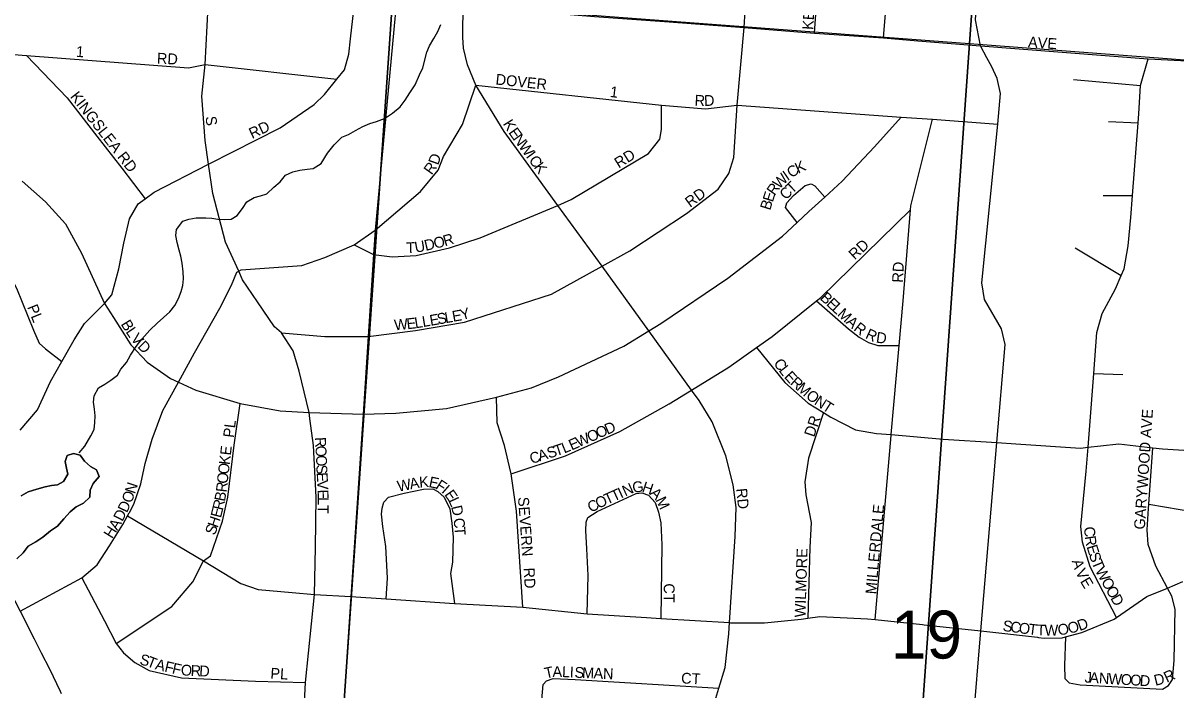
# Model space of a CAD drawing. Extents: x 0 to 34, y 0 to 22.
# Drawn here: x 4.06 to 5.068, y 19.645 to 20.227 of the extents above; entities that cross this region are included whole.
import ezdxf

# ---------------------------------------------------------------- set-up
doc = ezdxf.new("R2010")
doc.units = 0
for name, color, linetype in [('GM_X_City_Street', 7, 'Continuous'), ('GM_X_City_Street_Text', 7, 'Continuous'), ('GM_X_Minor_Lake', 7, 'Continuous'), ('GM_X_Section', 7, 'Continuous'), ('GM_X_Section_Text', 7, 'Continuous'), ('GM_X_Township', 7, 'Continuous'), ('GM_X_US_Route', 7, 'Continuous')]:
    doc.layers.add(name, color=color, linetype=linetype)

msp = doc.modelspace()

# ---------------------------------------------------------------- linework, layer by layer
at = {"layer": 'GM_X_City_Street'}
for points in [[(4.6908, 20.2235), (4.6971, 20.3256), (4.7014, 20.3449), (4.7083, 20.3621), (4.7157, 20.3809), (4.7159, 20.3828), (4.7163, 20.3877), (4.7225, 20.4452), (4.7281, 20.4967), (4.734, 20.551), (4.7395, 20.6016), (4.7397, 20.603), (4.7454, 20.6575), (4.7514, 20.7146), (4.7558, 20.7568), (4.7554, 20.7682), (4.7496, 20.7774), (4.7304, 20.8076), (4.7253, 20.8173), (4.7253, 20.8196), (4.7291, 20.8815)], [(4.8977, 20.2074), (4.8932, 20.2301), (4.9003, 20.33), (4.9074, 20.4285), (4.9121, 20.5032), (4.9139, 20.5324), (4.9208, 20.6443), (4.9237, 20.6899), (4.9244, 20.6989), (4.9384, 20.8789)], [(4.8128, 20.2144), (4.818, 20.2779), (4.8184, 20.3024), (4.823, 20.3174), (4.8309, 20.3384), (4.8395, 20.3614), (4.8435, 20.3818), (4.8426, 20.3913), (4.8402, 20.3997)], [(4.7525, 20.2185), (4.7588, 20.3095), (4.7569, 20.325), (4.7614, 20.337), (4.7725, 20.3626)], [(3.7534, 20.2931), (3.8331, 20.288), (3.8627, 20.2861), (3.9076, 20.2829), (3.9707, 20.2779), (4.0334, 20.2728), (4.097, 20.2682), (4.1591, 20.2638), (4.2232, 20.259), (4.2902, 20.2539), (4.3507, 20.2493), (4.387, 20.2468), (4.4457, 20.2423), (4.5601, 20.2332), (4.6254, 20.2285), (4.6908, 20.2235), (4.7525, 20.2185), (4.8128, 20.2144), (4.8427, 20.2119)], [(4.3112, 19.8818), (4.3105, 19.8869), (4.3017, 19.923), (4.2966, 19.9408), (4.2863, 19.9566), (4.2801, 19.962), (4.2654, 19.9837), (4.2522, 20.0031), (4.2489, 20.0105), (4.2375, 20.0358), (4.2263, 20.0783), (4.2226, 20.104), (4.2196, 20.1247), (4.2167, 20.1634), (4.2196, 20.191), (4.2232, 20.259)], [(4.0578, 19.8716), (4.073, 19.8894), (4.0844, 19.9141), (4.0943, 19.9316), (4.105, 19.9504), (4.1141, 19.9648), (4.1316, 19.9822), (4.1381, 19.9898), (4.1442, 20.0126), (4.1485, 20.0349), (4.1535, 20.0562), (4.1611, 20.0695), (4.1671, 20.0738), (4.1751, 20.0796), (4.2226, 20.104), (4.223, 20.1042), (4.2852, 20.1359), (4.3148, 20.1562), (4.3239, 20.1649), (4.3346, 20.1782), (4.3414, 20.1865), (4.3453, 20.2002), (4.3468, 20.2135), (4.3507, 20.2493)], [(4.6625, 19.6256), (4.6687, 19.646), (4.6744, 19.6642), (4.6775, 19.6935), (4.6781, 19.7034), (4.6831, 19.7785), (4.6839, 19.8039), (4.6813, 19.8237), (4.675, 19.8491), (4.6629, 19.8788), (4.6516, 19.8974), (4.645, 19.9066), (4.6076, 19.9583), (4.5666, 20.0148), (4.5281, 20.068), (4.4811, 20.1326), (4.4564, 20.1731), (4.4489, 20.1908), (4.4456, 20.2055), (4.4449, 20.215), (4.4449, 20.2273), (4.4457, 20.2423)], [(4.2863, 19.9566), (4.3243, 19.9534), (4.3621, 19.9533), (4.4034, 19.9586), (4.4464, 19.966), (4.5223, 19.9904), (4.5666, 20.0148), (4.591, 20.0282), (4.6404, 20.061), (4.6681, 20.0822), (4.6776, 20.0958), (4.6819, 20.1099), (4.6848, 20.1556), (4.6908, 20.2235)], [(3.9615, 20.2216), (3.9804, 20.2082), (3.9902, 20.2036), (4.0111, 20.2032), (4.0633, 20.1991), (4.205, 20.1881), (4.2196, 20.191), (4.3346, 20.1782)], [(4.8427, 20.2119), (4.8977, 20.2074), (5.0441, 20.196), (5.0784, 20.1943), (5.1422, 20.1904), (5.1677, 20.188), (5.203, 20.1861), (5.2651, 20.1817), (5.3905, 20.173), (5.4941, 20.1636), (5.6037, 20.1551), (5.6314, 20.1529)], [(4.905, 19.5357), (4.9012, 19.5594), (4.8985, 19.5762), (4.8896, 19.5952), (4.891, 19.6145), (4.8911, 19.6152), (4.8979, 19.6961), (4.9119, 19.8608), (4.9191, 19.9465), (4.9159, 19.9602), (4.9011, 19.9858), (4.8986, 20.0003), (4.9127, 20.1391), (4.9152, 20.1659), (4.9122, 20.179), (4.9074, 20.189), (4.903, 20.1971), (4.8977, 20.2074)], [(4.0633, 20.1991), (4.0989, 20.1619), (4.1249, 20.1284), (4.1468, 20.1006), (4.1671, 20.0738)], [(5.0164, 19.7078), (4.9936, 19.7521), (4.9868, 19.7737), (4.9853, 19.7874), (4.99, 19.8356), (4.9916, 19.8566), (4.9967, 19.9212), (4.9994, 19.9568), (5.004, 19.9735), (5.0155, 19.9951), (5.0205, 20.0067), (5.0231, 20.0125), (5.0266, 20.0326), (5.0289, 20.0573), (5.0304, 20.0767), (5.0354, 20.1401), (5.036, 20.1481), (5.0376, 20.1727), (5.0441, 20.196)], [(4.1532, 19.7992), (4.1534, 19.7997), (4.1572, 19.8068), (4.1633, 19.8246), (4.1672, 19.8424), (4.1733, 19.8637), (4.1825, 19.8887), (4.1962, 19.9136), (4.2103, 19.9391), (4.2324, 19.9781), (4.2427, 19.9982), (4.2473, 20.0096), (4.2489, 20.0105), (4.2511, 20.0118), (4.3041, 20.0155), (4.3241, 20.0224), (4.35, 20.0335), (4.3683, 20.0465), (4.4079, 20.0802), (4.4234, 20.0987), (4.428, 20.1107), (4.4447, 20.1387), (4.4564, 20.1731)], [(4.4564, 20.1731), (4.6187, 20.1555), (4.657, 20.1525), (4.6848, 20.1556), (4.8283, 20.145), (4.8555, 20.1434), (4.9127, 20.1391)], [(4.9788, 20.1779), (5.0376, 20.1727)], [(4.35, 20.0335), (4.3668, 20.0251), (4.3831, 20.0231), (4.4042, 20.0243), (4.4333, 20.0308), (4.46, 20.0396), (4.5281, 20.068), (4.5396, 20.0731), (4.6072, 20.1135), (4.6171, 20.126), (4.6186, 20.1344), (4.6187, 20.1555)], [(4.0596, 20.0891), (4.08, 20.0712), (4.0974, 20.0518), (4.1113, 20.0263), (4.1316, 19.9822), (4.1395, 19.9701), (4.1546, 19.9461), (4.169, 19.9309), (4.1894, 19.9168), (4.1962, 19.9136), (4.2113, 19.9064), (4.2503, 19.8949), (4.2852, 19.8885), (4.3105, 19.8869), (4.3576, 19.8857), (4.3862, 19.8863), (4.4305, 19.8904), (4.4742, 19.9005), (4.505, 19.9086), (4.5285, 19.9183), (4.5858, 19.9451), (4.6076, 19.9583), (4.6181, 19.9647), (4.6766, 20.0044), (4.7244, 20.041), (4.7374, 20.0531), (4.7476, 20.0626), (4.7615, 20.0753), (4.7765, 20.0891), (4.805, 20.1193), (4.8283, 20.145)], [(4.8056, 19.706), (4.8194, 19.8669), (4.8195, 19.8677), (4.8265, 19.9456), (4.83, 19.9845), (4.8364, 20.0641), (4.8367, 20.0676), (4.8555, 20.1434)], [(5.0094, 20.1413), (5.0354, 20.1401)], [(3.8939, 20.1247), (3.9115, 20.106), (3.9531, 20.0758), (4.0393, 20.0178), (4.0476, 20.0087), (4.0547, 19.9958), (4.0694, 19.9589), (4.0743, 19.9475), (4.08, 19.9426), (4.0943, 19.9316)], [(4.7374, 20.0531), (4.7272, 20.0661), (4.7283, 20.0702), (4.734, 20.0767), (4.7443, 20.0854), (4.7496, 20.0869), (4.7526, 20.085), (4.7615, 20.0753)], [(5.0047, 20.0768), (5.0304, 20.0767)], [(4.4871, 19.8333), (4.5348, 19.8492), (4.5823, 19.8703), (4.6252, 19.8945), (4.645, 19.9066), (4.6776, 19.9266), (4.7017, 19.9438), (4.7153, 19.9534), (4.7543, 19.9846), (4.7579, 19.9875), (4.8364, 20.0641)], [(4.9803, 20.0309), (5.0205, 20.0067)], [(4.7543, 19.9846), (4.7821, 19.9601), (4.7915, 19.9528), (4.7995, 19.9482), (4.8078, 19.9456), (4.8265, 19.9456)], [(4.7017, 19.9438), (4.7265, 19.9132), (4.747, 19.8952), (4.7603, 19.887), (4.7667, 19.883), (4.7883, 19.8719), (4.8065, 19.8688), (4.8195, 19.8677), (4.8649, 19.8637), (4.9119, 19.8608), (4.9286, 19.8597), (4.9851, 19.8558), (4.9916, 19.8566), (5.0026, 19.858), (5.0185, 19.8595), (5.0483, 19.8561), (5.0568, 19.8552), (5.1362, 19.8504)], [(4.9967, 19.9212), (5.0221, 19.9202)], [(4.1418, 19.6852), (4.1903, 19.7175), (4.2089, 19.739), (4.218, 19.7574), (4.2241, 19.7618), (4.2348, 19.7921), (4.2395, 19.813), (4.2449, 19.8585), (4.2503, 19.8949)], [(4.4974, 19.7169), (4.4918, 19.8007), (4.4871, 19.8333), (4.487, 19.8345), (4.4814, 19.8581), (4.475, 19.8779), (4.4742, 19.9005)], [(4.3809, 19.4652), (4.3713, 19.4859), (4.3604, 19.4991), (4.3474, 19.5119), (4.3336, 19.5245), (4.3232, 19.5402), (4.3146, 19.5588), (4.3093, 19.5755), (4.3058, 19.59), (4.3051, 19.6047), (4.3074, 19.651), (4.3153, 19.728), (4.3162, 19.7691), (4.3165, 19.8131), (4.3143, 19.8581), (4.3112, 19.8818)], [(4.7603, 19.887), (4.7472, 19.847), (4.7441, 19.8265), (4.7449, 19.8151), (4.7494, 19.7908), (4.7482, 19.7691), (4.7467, 19.7073)], [(5.062, 19.6485), (5.0654, 19.6538), (5.067, 19.6702), (5.0678, 19.715), (5.0648, 19.7264), (5.061, 19.7336), (5.0509, 19.7526), (5.0441, 19.7716), (5.0434, 19.7846), (5.0446, 19.8032), (5.0448, 19.8068), (5.0483, 19.8561)], [(4.378, 19.7241), (4.379, 19.7423), (4.3776, 19.77), (4.375, 19.7875), (4.3739, 19.7981), (4.3743, 19.8034), (4.3759, 19.8087), (4.38, 19.8129), (4.3937, 19.8166), (4.4104, 19.82), (4.4187, 19.8203), (4.4229, 19.8181), (4.4285, 19.8131), (4.4334, 19.8028), (4.4353, 19.7903), (4.4364, 19.7782), (4.4359, 19.7561), (4.434, 19.7463), (4.4375, 19.72)], [(4.5536, 19.711), (4.5545, 19.7447), (4.5534, 19.7679), (4.5524, 19.7838), (4.5528, 19.7911), (4.5543, 19.7952), (4.5623, 19.8005), (4.5964, 19.8163), (4.6013, 19.8167), (4.6074, 19.8148), (4.6131, 19.8083), (4.6161, 19.8), (4.6179, 19.7905), (4.619, 19.7715), (4.6181, 19.707)], [(5.0448, 19.8068), (5.0859, 19.8)], [(4.0577, 19.7133), (4.1116, 19.7426), (4.1251, 19.7539), (4.1359, 19.7704), (4.1477, 19.789), (4.1518, 19.7966), (4.1532, 19.7992)], [(4.1518, 19.7966), (4.218, 19.7574), (4.2507, 19.7375), (4.2659, 19.7324), (4.2957, 19.7297)], [(4.1116, 19.7426), (4.1315, 19.7048), (4.1418, 19.6852), (4.1482, 19.6771), (4.1581, 19.6686), (4.1707, 19.6616), (4.1988, 19.6552), (4.2636, 19.6523), (4.3074, 19.651)], [(4.2957, 19.7297), (4.3153, 19.728), (4.347, 19.7261), (4.378, 19.7241), (4.4375, 19.72), (4.4974, 19.7169), (4.5536, 19.711), (4.6055, 19.7078), (4.6181, 19.707), (4.6781, 19.7034), (4.679, 19.7033), (4.7086, 19.7032), (4.7408, 19.7065), (4.7467, 19.7073), (4.7571, 19.7088), (4.7988, 19.7067), (4.8056, 19.706), (4.8469, 19.7016), (4.8482, 19.7015)], [(4.9484, 19.6905), (4.9533, 19.6899), (4.9689, 19.6902), (4.9719, 19.691), (4.9863, 19.6947), (5.0144, 19.7064), (5.0164, 19.7078), (5.0429, 19.7261), (5.061, 19.7336), (5.0744, 19.7392)], [(4.8482, 19.7015), (4.8979, 19.6961), (4.9473, 19.6906), (4.9484, 19.6905)], [(4.9719, 19.691), (4.971, 19.6659), (4.9713, 19.6545), (4.9751, 19.6507), (4.9846, 19.6491), (5.0567, 19.6451), (5.062, 19.6485)], [(4.5108, 19.5988), (4.5152, 19.6492), (4.5182, 19.6526), (4.5239, 19.6545), (4.5432, 19.6537), (4.6687, 19.646)]]:
    msp.add_lwpolyline(points, dxfattribs=at)
at = {"layer": 'GM_X_Minor_Lake'}
for points in [[(4.1094, 19.8517), (4.1144, 19.8575), (4.1197, 19.8666), (4.1224, 19.8723), (4.1231, 19.8784), (4.1235, 19.8841), (4.1227, 19.8898), (4.122, 19.8959), (4.1224, 19.9016), (4.1262, 19.9085), (4.1319, 19.9119), (4.1372, 19.9154), (4.1429, 19.9196), (4.1459, 19.9249), (4.1509, 19.9306), (4.1543, 19.9371), (4.1593, 19.9447), (4.1642, 19.9512), (4.1711, 19.9589), (4.1775, 19.965), (4.1832, 19.9699), (4.1886, 19.9749), (4.1931, 19.9806), (4.1962, 19.9867), (4.1985, 19.9928), (4.2, 19.9981), (4.2007, 20.0039), (4.2004, 20.0099), (4.1996, 20.0176), (4.1984, 20.0237), (4.1969, 20.029), (4.195, 20.0355), (4.1939, 20.0416), (4.1946, 20.0469), (4.2, 20.0541), (4.2053, 20.056), (4.2118, 20.0572), (4.2201, 20.0572), (4.2255, 20.0568), (4.2308, 20.0561), (4.2361, 20.0557), (4.2422, 20.0561), (4.2475, 20.0591), (4.2521, 20.0653), (4.2559, 20.071), (4.2624, 20.0748), (4.2681, 20.0763), (4.2734, 20.0782), (4.2795, 20.084), (4.2852, 20.0885), (4.2898, 20.0943), (4.2962, 20.0973), (4.3023, 20.0988), (4.3088, 20.0996), (4.3141, 20.1004), (4.321, 20.1046), (4.3267, 20.1137), (4.3324, 20.121), (4.3392, 20.1275), (4.3449, 20.1301), (4.351, 20.1336), (4.3575, 20.137), (4.3636, 20.1397), (4.3693, 20.1412), (4.3765, 20.1439), (4.3834, 20.1485), (4.3902, 20.1542), (4.3944, 20.1599), (4.3986, 20.1664), (4.4031, 20.1733), (4.407, 20.182), (4.41, 20.1881), (4.4134, 20.2018), (4.4157, 20.2076), (4.4195, 20.214), (4.4229, 20.2201), (4.4256, 20.2262)], [(4.055, 19.7591), (4.0604, 19.7644), (4.0649, 19.7701), (4.0714, 19.774), (4.0775, 19.7782), (4.0843, 19.7835), (4.0904, 19.7877), (4.0961, 19.7942), (4.1014, 19.8003), (4.1068, 19.8045), (4.1132, 19.8079), (4.1186, 19.8129), (4.1189, 19.819), (4.1216, 19.8251), (4.1269, 19.8312), (4.1247, 19.8369), (4.1193, 19.8399), (4.114, 19.8445), (4.1102, 19.8498), (4.1045, 19.8513), (4.0988, 19.8494), (4.0973, 19.8441), (4.0984, 19.8384), (4.0995, 19.833), (4.0957, 19.8266), (4.0904, 19.8239), (4.0851, 19.8231), (4.0798, 19.822), (4.0725, 19.8201), (4.0649, 19.8178), (4.0588, 19.8143)], [(4.0588, 19.8143), (4.0649, 19.8178), (4.0725, 19.8201), (4.0798, 19.822), (4.0851, 19.8231), (4.0904, 19.8239), (4.0957, 19.8266), (4.0995, 19.833), (4.0984, 19.8384), (4.0973, 19.8441), (4.0988, 19.8494), (4.1045, 19.8513), (4.1102, 19.8498), (4.114, 19.8445), (4.1193, 19.8399), (4.1247, 19.8369), (4.1269, 19.8312), (4.1216, 19.8251), (4.1189, 19.819), (4.1186, 19.8129), (4.1132, 19.8079), (4.1068, 19.8045), (4.1014, 19.8003), (4.0961, 19.7942), (4.0904, 19.7877), (4.0843, 19.7835), (4.0775, 19.7782), (4.0714, 19.774), (4.0649, 19.7701), (4.0604, 19.7644), (4.055, 19.7591)]]:
    msp.add_lwpolyline(points, dxfattribs=at)
at = {"layer": 'GM_X_Section'}
for points in [[(4.4299, 20.9), (4.3834, 20.2477), (4.8879, 20.2095), (4.9378, 20.9)], [(4.9378, 20.9), (4.8879, 20.2095), (5.3911, 20.1713), (5.4444, 20.9)]]:
    msp.add_lwpolyline(points, dxfattribs=at)
for points in [[(4.3834, 20.2477), (4.3138, 19.2385), (3.8108, 19.2741), (3.8817, 20.285)], [(4.3834, 20.2477), (4.8879, 20.2095), (4.8168, 19.2029), (4.3138, 19.2385)], [(4.8879, 20.2095), (5.3911, 20.1713), (5.3184, 19.1674), (4.8168, 19.2029)]]:
    msp.add_lwpolyline(points, close=True, dxfattribs=at)
at = {"layer": 'GM_X_Township'}
msp.add_lwpolyline([(4.4299, 20.9), (4.4298, 20.8976), (4.418, 20.756), (4.4047, 20.5692), (4.3966, 20.3992), (4.3872, 20.2493), (4.387, 20.2468), (4.3683, 20.0465), (4.3668, 20.0251), (4.3621, 19.9533), (4.3576, 19.8857), (4.347, 19.726), (4.3386, 19.5994), (4.3336, 19.5245), (4.3259, 19.4084), (4.3192, 19.3241), (4.316, 19.2834), (4.3079, 19.1898), (4.306, 19.1736), (4.2991, 19.0875), (4.2793, 18.8701), (4.2426, 18.2767)], dxfattribs=at)
at = {"layer": 'GM_X_US_Route'}
for points in [[(3.7534, 20.2931), (3.7557, 20.2876), (3.7826, 20.2352), (3.8043, 20.195), (3.8254, 20.1559), (3.8549, 20.0997), (3.894, 20.0254), (3.9134, 19.9888), (3.9944, 19.8346), (4.0436, 19.741), (4.0577, 19.7133), (4.07, 19.6892), (4.0763, 19.6771)], [(4.0763, 19.6771), (4.0836, 19.663), (4.0929, 19.6436), (4.0938, 19.6414)]]:
    msp.add_lwpolyline(points, dxfattribs=at)

# ---------------------------------------------------------------- texts
at = {"layer": 'GM_X_City_Street_Text'}
for s, rotation, p in [('KENILWORTH', 86.3084, (4.7512, 20.2212)), ('AVE', 356.0569, (4.9389, 20.2062)), ('1', 356.6358, (4.1064, 20.1978)), ('RD', 356.989, (4.1772, 20.192)), ('DOVER', 353.9264, (4.4732, 20.1737)), ('KINGSLEA RD', 307.9839, (4.1011, 20.163)), ('1', 353.2931, (4.5732, 20.1628)), ('R', 356.1116, (4.6473, 20.1553)), ('D', 2.5449, (4.656, 20.1548)), ('S', 277.1486, (4.2198, 20.1455)), ('K', 301.9197, (4.4796, 20.1394)), ('RD', 25.2017, (4.2606, 20.126)), ('E', 305.6042, (4.4844, 20.1317)), ('N', 306.3062, (4.4883, 20.1262)), ('W', 306.3103, (4.4932, 20.1195)), ('D', 70.4547, (4.4233, 20.1027)), ('I', 306.3103, (4.4997, 20.1108)), ('RD', 32.0066, (4.5812, 20.1001)), ('R', 54.4172, (4.4176, 20.0941)), ('C', 306.3113, (4.5021, 20.1074)), ('K', 306.2973, (4.5066, 20.1014)), ('C', 34.5723, (4.7323, 20.0916)), ('K', 25.2942, (4.7381, 20.0956)), ('W', 45.3923, (4.7216, 20.0818)), ('I', 34.5873, (4.7288, 20.0892)), ('RD', 36.2589, (4.6436, 20.0658)), ('R', 54.5385, (4.7175, 20.076)), ('C', 47.6626, (4.7278, 20.0723)), ('T', 43.551, (4.7327, 20.0777)), ('B', 72.6634, (4.7136, 20.0632)), ('E', 72.6623, (4.7159, 20.0703)), ('R', 16.6424, (4.4292, 20.0322)), ('T', 2.2961, (4.3956, 20.0262)), ('U', 10.1183, (4.4036, 20.0266)), ('D', 13.3842, (4.4124, 20.0282)), ('O', 13.2993, (4.4205, 20.0301)), ('RD', 42.8801, (4.7876, 20.0199)), ('RD', 86.989, (4.8297, 20.0003)), ('B', 316.9406, (4.7566, 19.9864)), ('PL', 291.8039, (4.0638, 19.9792)), ('E', 316.9272, (4.7621, 19.9813)), ('L', 316.9449, (4.767, 19.9768)), ('L', 9.8202, (4.4101, 19.9616)), ('E', 9.87, (4.4167, 19.9627)), ('S', 9.895, (4.4232, 19.9639)), ('L', 9.895, (4.4298, 19.965)), ('E', 10.1602, (4.4364, 19.9662)), ('Y', 15.7427, (4.444, 19.9676)), ('M', 316.9432, (4.7718, 19.9722)), ('B', 301.753, (4.1455, 19.9643)), ('L', 304.3424, (4.1497, 19.9575)), ('W', 5.5232, (4.3853, 19.9587)), ('E', 6.3213, (4.3962, 19.9597)), ('L', 9.0791, (4.4034, 19.9605)), ('A', 318.0932, (4.7793, 19.9653)), ('R', 321.661, (4.786, 19.9593)), ('V', 309.5211, (4.154, 19.9513)), ('R', 335.1719, (4.7962, 19.9522)), ('D', 351.6588, (4.8058, 19.9482)), ('D', 314.6999, (4.1599, 19.9442)), ('C', 308.0454, (4.7161, 19.9297)), ('L', 308.0283, (4.7207, 19.9237)), ('E', 312.6103, (4.7253, 19.9179)), ('R', 318.4477, (4.7306, 19.9122)), ('M', 318.7744, (4.7362, 19.9072)), ('O', 321.6682, (4.7442, 19.9003)), ('N', 326.9402, (4.7515, 19.8946)), ('T', 327.2885, (4.7585, 19.89)), ('DR', 71.5614, (4.7521, 19.865)), ('GARYWOOD AVE', 86.0558, (5.0412, 19.7845)), ('PL', 82.8649, (4.2446, 19.8646)), ('O', 23.7201, (4.556, 19.8607)), ('O', 23.7095, (4.5636, 19.8641)), ('D', 23.6895, (4.5713, 19.8674)), ('R', 272.7205, (4.3156, 19.8653)), ('L', 22.0962, (4.5335, 19.8511)), ('E', 23.616, (4.54, 19.8537)), ('W', 23.7019, (4.5461, 19.8564)), ('E', 83.5495, (4.242, 19.8492)), ('O', 272.7107, (4.316, 19.8578)), ('C', 17.4902, (4.505, 19.8419)), ('A', 17.4948, (4.5121, 19.8442)), ('S', 17.5048, (4.5201, 19.8467)), ('T', 18.2271, (4.5265, 19.8487)), ('O', 83.5484, (4.2401, 19.8326)), ('K', 83.5484, (4.241, 19.8409)), ('O', 272.7102, (4.3164, 19.8495)), ('S', 272.7055, (4.3167, 19.8412)), ('O', 83.5391, (4.2391, 19.8244)), ('E', 272.7055, (4.3171, 19.8345)), ('K', 5.0559, (4.4071, 19.8213)), ('E', 347.9453, (4.4146, 19.822)), ('N', 71.8352, (4.1581, 19.8154)), ('R', 83.5608, (4.2383, 19.8169)), ('V', 272.7327, (4.3174, 19.8278)), ('W', 10.4823, (4.3885, 19.8178)), ('A', 10.4612, (4.3991, 19.8198)), ('F', 327.3403, (4.4203, 19.821)), ('I', 318.6496, (4.4256, 19.8176)), ('T', 24.5366, (4.577, 19.809)), ('I', 24.5745, (4.5831, 19.8118)), ('N', 24.5416, (4.5869, 19.8135)), ('G', 6.9244, (4.5937, 19.8168)), ('H', 341.6549, (4.6009, 19.8179)), ('RD', 275.7074, (4.6839, 19.8204)), ('O', 69.7842, (4.1551, 19.8072)), ('R', 76.684, (4.235, 19.801)), ('B', 79.5959, (4.2368, 19.8088)), ('E', 272.2404, (4.3178, 19.8195)), ('L', 270.5738, (4.318, 19.813)), ('E', 304.9629, (4.4284, 19.8153)), ('L', 294.903, (4.432, 19.8102)), ('SEVERN', 274.2315, (4.4931, 19.8129)), ('C', 28.4767, (4.557, 19.7992)), ('O', 25.2453, (4.5634, 19.8027)), ('T', 24.5728, (4.571, 19.8063)), ('A', 315.0773, (4.6078, 19.8159)), ('M', 295.3921, (4.6132, 19.8107)), ('D', 62.9764, (4.1472, 19.7912)), ('D', 64.3068, (4.1511, 19.7988)), ('E', 75.7565, (4.2333, 19.7944)), ('T', 270.0273, (4.3181, 19.8063)), ('D', 282.7587, (4.4346, 19.8047)), ('MILLERDALE', 84.864, (4.8063, 19.7279)), ('A', 59.3811, (4.1427, 19.7834)), ('H', 71.2011, (4.2304, 19.7857)), ('C', 275.9353, (4.4367, 19.7944)), ('H', 58.1104, (4.1381, 19.7762)), ('S', 69.6038, (4.228, 19.7792)), ('T', 273.8286, (4.4375, 19.787)), ('C', 273.9126, (4.9881, 19.787)), ('R', 278.8607, (4.9887, 19.7786)), ('E', 287.0975, (4.9902, 19.7698)), ('WILMORE', 88.2652, (4.7445, 19.7078)), ('S', 287.3772, (4.9922, 19.7633)), ('RD', 273.0225, (4.4981, 19.7512)), ('A', 287.2667, (4.9773, 19.7572)), ('V', 295.5678, (4.9804, 19.7478)), ('T', 292.5076, (4.9945, 19.7561)), ('W', 298.9657, (4.9975, 19.7489)), ('E', 300.669, (4.9844, 19.7395)), ('O', 299.0762, (5.0028, 19.7394)), ('CT', 270, (4.6206, 19.7377)), ('O', 299.0482, (5.0068, 19.7321)), ('D', 299.0608, (5.0109, 19.7248)), ('S', 352.3837, (4.9166, 19.6962)), ('C', 352.3508, (4.9232, 19.6953)), ('O', 352.3723, (4.9306, 19.6943)), ('T', 353.0881, (4.939, 19.6932)), ('T', 357.7951, (4.9465, 19.6923)), ('W', 0.2141, (4.9536, 19.692)), ('O', 8.1708, (4.9658, 19.6922)), ('O', 14.0477, (4.9751, 19.6936)), ('D', 20.4232, (4.9843, 19.6959)), ('S', 346.1493, (4.1617, 19.667)), ('T', 338.9899, (4.1678, 19.6655)), ('A', 346.2267, (4.1753, 19.6627)), ('F', 346.9282, (4.1835, 19.6607)), ('F', 347.5217, (4.1901, 19.6591)), ('O', 355.094, (4.198, 19.6575)), ('R', 358.0695, (4.2068, 19.6568)), ('D', 358.0787, (4.2143, 19.6565)), ('PL', 356.4262, (4.2764, 19.6545)), ('T', 12.194, (4.5173, 19.6544)), ('A', 0.4153, (4.5233, 19.6558)), ('L', 357.4855, (4.5315, 19.6558)), ('I', 357.4193, (4.5382, 19.6555)), ('S', 357.4036, (4.5424, 19.6553)), ('M', 357.3941, (4.549, 19.655)), ('A', 357.4033, (4.559, 19.6546)), ('N', 357.3984, (4.5673, 19.6542)), ('CT', 356.8215, (4.6356, 19.6503)), ('J', 356.5928, (4.9884, 19.6511)), ('A', 356.5928, (4.9925, 19.6508)), ('N', 356.5928, (5.0009, 19.6503)), ('W', 356.5928, (5.0092, 19.6498)), ('R', 24.814, (5.0605, 19.6507)), ('O', 356.5928, (5.02, 19.6492)), ('O', 356.5928, (5.0283, 19.6487)), ('D', 356.5928, (5.0366, 19.6482)), ('D', 13.5255, (5.0505, 19.6481))]:
    msp.add_text(s, height=0.00947, rotation=rotation, dxfattribs=at).set_placement(p)
at = {"layer": 'GM_X_Section_Text'}
msp.add_text('19', height=0.04186, rotation=0, dxfattribs=at).set_placement((4.8192, 19.672))

doc.saveas('drawing.dxf')
